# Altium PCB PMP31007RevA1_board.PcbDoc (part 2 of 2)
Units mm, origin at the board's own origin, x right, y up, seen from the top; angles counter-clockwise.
Board outline 45.72 x 49.53 mm, 2 copper layers (Top Layer, Bottom Layer), stack 1.575 mm thick; 68 components, 31 nets, 155 pads, 66 vias.
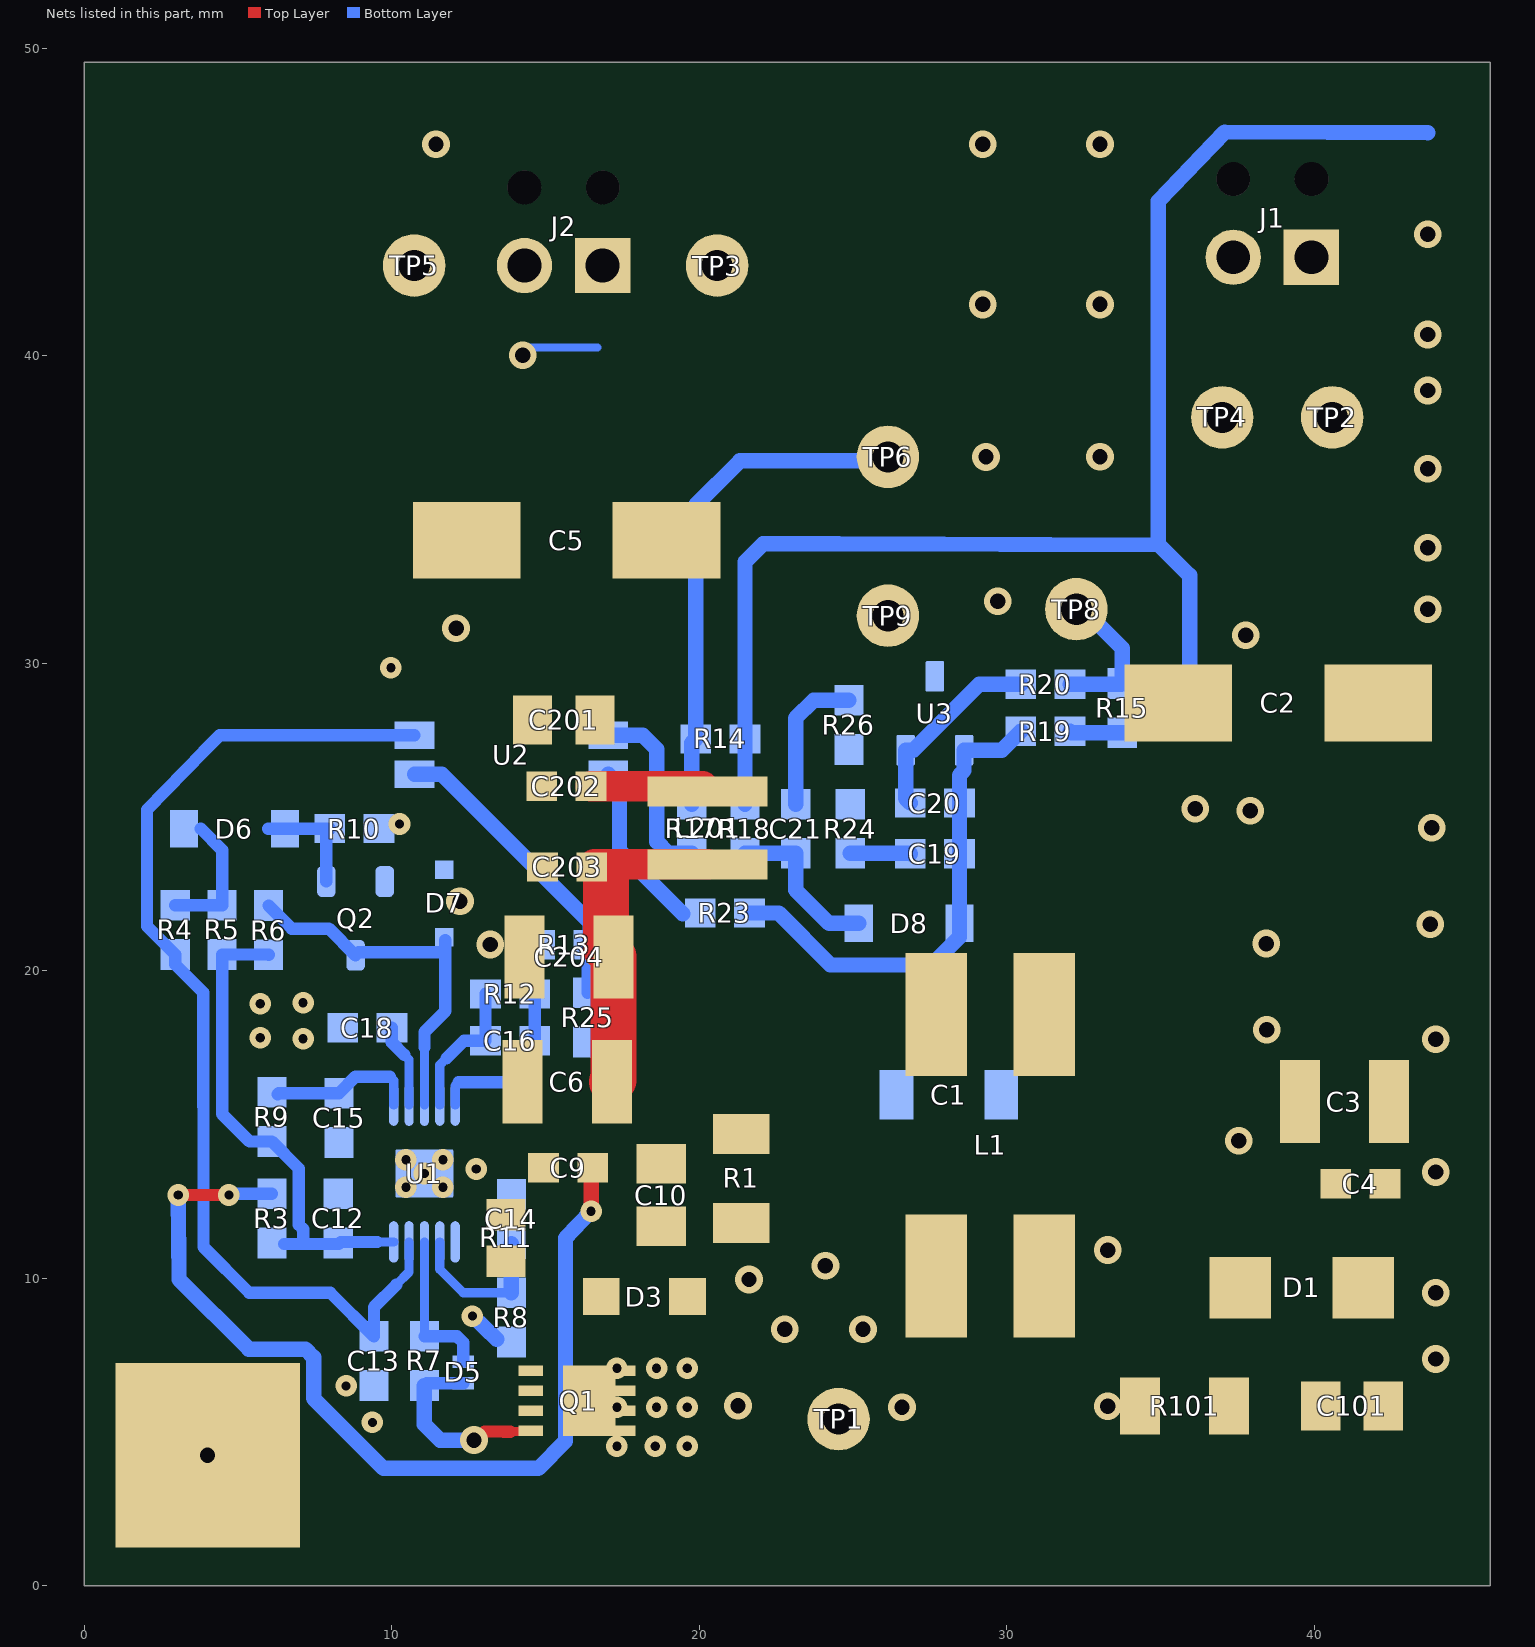
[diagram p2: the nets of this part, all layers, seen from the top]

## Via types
v1: diameter 0.9, hole 0.5, Top Layer to Bottom Layer, tented top, 21 vias
v2: diameter 0.7, hole 0.3, Top Layer to Bottom Layer, 18 vias
v3: diameter 0.9, hole 0.5, Top Layer to Bottom Layer, 17 vias
v4: diameter 0.7, hole 0.3, Top Layer to Bottom Layer, tented bottom, 9 vias
v5: diameter 0.9, hole 0.5, Top Layer to Bottom Layer, tented bottom, 1 vias

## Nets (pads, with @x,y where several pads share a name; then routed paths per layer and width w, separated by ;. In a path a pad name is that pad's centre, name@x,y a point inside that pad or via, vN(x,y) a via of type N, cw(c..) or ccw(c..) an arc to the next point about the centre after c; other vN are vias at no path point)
GND: C1.2 C5.2 C6.2 C9.2 C12.2 C13.2 C14.2 C15.2 C18.2 C201.2 C202.2 C203.2 C204.2 D7.2 J2.2 pad.1 Q2.2 R10.1 R11.1 R25.1 TP5.1 U1.6 U1.11 | length 2.5
  Bottom Layer w0.254: v3@14.137,40.259 16.681,40.259
  other v2: 9.363,5.305 10.456,12.949 11.656,12.949 11.056,13.399 10.456,13.849 11.656,13.849
  other v3: 13.193,20.846 12.084,31.126 14.251,40.005 11.43,46.869
  other v4: 8.508,6.492 12.744,13.545 7.111,17.78 5.714,17.817 5.714,18.923 7.111,18.954 10.245,24.765 9.966,29.845
  other v5: 12.213,22.252
GND2: C1.1 C2.2 C3.2 C4.2 C21.2 J1.2 L1.4 R26.1 TP4.1 TP9.1 U3.3 | length 4.8
  Bottom Layer w0.5: C21.2@23.13,25.41 23.13,28.21 23.706,28.786 R26.1@24.86,28.786
  other v1: 37.914,25.201 36.122,25.26 37.762,30.898 29.698,32.004 29.319,36.703 33.023,36.709 29.213,41.662 33.026,41.662 29.213,46.869 33.023,46.869
  other v3: 37.534,14.469 38.449,18.072 38.429,20.876
NetC6_1: C6.1 C9.1 C10.1 C203.1 C204.1 L1.3 L201.2 R1.2 R3.2 | length 41.4
  Top Layer w0.254: C9.1@16.475,13.533 C9.1@16.531,13.589 ; C203.1@16.493,23.368 C203.1@16.578,23.453
  Top Layer w0.4: v2(3.047,12.7) v4(4.698,12.7)
  Top Layer w0.5: v2(16.475,12.171) C9.1@16.475,13.533
  Top Layer w1: C203.1@16.578,23.453 L201.2@20.266,23.453
  Top Layer w1.5: C204.1@16.959,20.701 16.959,22.844 ; C6.1@17.151,16.383 17.209,16.441 C204.1@17.209,20.447
  Bottom Layer w0.4: v4(4.698,12.7) 4.736,12.738 R3.2@6.095,12.738
  Bottom Layer w0.5: v2(3.047,12.7) 3.076,9.953 5.343,7.685 7.187,7.685 7.451,7.422 7.451,6.085 9.726,3.811 14.759,3.811 15.642,4.693 15.642,11.303 v2(16.475,12.171)
NetC10_2: C10.2 D3.1 R1.1
NetC12_1: C12.1 R3.1 R5.2 R6.2 R9.2 U1.10 | length 16
  Bottom Layer w0.3: 9.526,11.174 U1.10@10.056,11.174
  Bottom Layer w0.4: R6.2@5.988,20.513 5.98,20.521 R5.2@4.476,20.521 4.476,15.334 5.371,14.44 R9.2@6.095,14.44 6.97,13.565 6.97,11.731 7.111,11.59 7.111,11.108 ; R3.1@6.492,11.108 7.111,11.108 ; 9.526,11.174 8.336,11.174 8.27,11.108 7.111,11.108
NetC14_1: C14.1 R8.1 U1.7 | length 5.1
  Bottom Layer w0.3: U1.7@11.556,11.174 11.556,10.285 12.319,9.521 R8.1@13.884,9.521
  Bottom Layer w0.5: R8.1@13.884,9.521 C14.1@13.884,11.124
NetC15_1: C15.1 R9.1 U1.1 | length 4.9
  Bottom Layer w0.3: 9.927,16.549 10.056,16.42 U1.1@10.056,15.624
  Bottom Layer w0.4: R9.1@6.284,15.972 6.322,16.01 C15.1@8.278,16.01 8.817,16.549 9.927,16.549
NetC16_1: C16.1 R12.2 U1.4 | length 4.6
  Bottom Layer w0.3: U1.4@11.556,15.624 11.556,16.93 11.77,17.145
  Bottom Layer w0.4: 11.77,17.145 12.342,17.717 C16.1@13.044,17.717 R12.2@13.044,19.241
NetC16_2: C16.2 R12.1 R13.2 U1.5 | length 7.4
  Bottom Layer w0.3: U1.5@12.056,15.624 12.056,16.256 12.163,16.364
  Bottom Layer w0.4: 12.163,16.364 13.975,16.364 14.644,17.032 C16.2@14.644,17.717 R12.1@14.644,19.241 14.644,20.685 R13.2@14.8,20.841
NetC18_1: C18.1 U1.2 | length 2.7
  Bottom Layer w0.3: 10.395,17.263 10.556,17.102 U1.2@10.556,15.624
  Bottom Layer w0.4: C18.1@9.997,18.138 9.997,17.661 10.395,17.263
NetC19_1: C19.1 R24.1 | length 2
  Bottom Layer w0.5: R24.1@24.902,23.81 26.839,23.81 C19.1@26.854,23.795
NetC19_2: C19.2 C20.1 D8.2 R19.1 R23.1 U3.1 | length 16.1
  Bottom Layer w0.5: R23.1@21.628,21.871 22.578,21.871 24.257,20.178 27.545,20.178 28.454,21.087 C19.2@28.454,23.795 C20.1@28.454,25.446 28.454,26.353 28.604,26.503 U3.1@28.604,27.167 29.833,27.167 R19.1@30.448,27.783
NetC20_2: C20.2 R20.1 R24.2 R26.2 U3.2 | length 6.4
  Bottom Layer w0.5: C20.2@26.854,25.446 26.704,25.596 U3.2@26.704,27.167 26.954,27.167 29.094,29.307 R20.1@30.448,29.307
NetC21_1: C21.1 D8.1 R18.1 | length 5.3
  Bottom Layer w0.5: R18.1@21.479,23.81 C21.1@23.13,23.81 23.13,22.62 24.216,21.533 D8.1@25.18,21.533
NetC101_2: C101.2 R101.2
NetD1_2: D1.2 L1.2 R101.1
  other v1: 33.277,5.829 33.277,10.909
NetD3_2: D3.2 L1.1 Q1.5 Q1.6 Q1.7 Q1.8 Q1.9 TP1.1
  other v1: 26.587,5.798 22.777,8.338 25.317,8.338 21.611,9.953 24.096,10.397
  other v2: 17.316,4.528 18.563,4.528 19.602,4.528 17.316,5.798 18.605,5.798 19.602,5.798 17.316,7.068 18.605,7.068 19.602,7.068
  other v3: 21.253,5.842
NetD5_1: D5.1 R7.2 U1.8 | length 5
  Bottom Layer w0.3: R7.2@11.056,8.103 U1.8@11.056,11.174
  Bottom Layer w0.4: R7.2@11.056,8.103 12.118,8.103 12.318,7.903 D5.1@12.318,7.282
NetD5_2: D5.2 Q1.4 R7.1 | length 6.6
  Top Layer w0.254: v3(12.668,4.73) 12.73,4.73 v3@13.007,5.007 ; 13.844,5.004 13.846,5.007
  Top Layer w0.3: 13.846,5.007 Q1.4@14.546,5.007
  Top Layer w0.4: v3@13.007,5.007 13.216,5.006 13.634,5.005 13.844,5.004
  Top Layer w0.5: v3(12.668,4.73) v3@12.811,4.587
  Bottom Layer w0.4: R7.1@11.056,6.503 11.135,6.582 D5.2@12.318,6.582
  Bottom Layer w0.5: R7.1@11.056,6.503 11.056,5.236 11.562,4.73 v3(12.668,4.73)
NetD6_1: D6.1 R4.1 R5.1 | length 4.3
  Bottom Layer w0.4: R4.1@2.952,22.121 R5.1@4.476,22.121 4.476,23.918 3.779,24.615
NetD6_2: D6.2 Q2.1 R10.2 | length 3.8
  Bottom Layer w0.4: 5.979,24.615 R10.2@7.978,24.615 7.866,24.503 Q2.1@7.866,22.894
NetD7_1: D7.1 Q2.3 R6.1 U1.3 | length 12
  Bottom Layer w0.3: U1.3@11.056,15.624 11.056,17.507
  Bottom Layer w0.4: R6.1@5.988,22.113 6.739,21.362 7.948,21.362 Q2.3@8.816,20.494 ; Q2.3@8.916,20.594 11.737,20.594 ; 11.056,17.507 11.056,18.003 11.737,18.684 D7.1@11.737,20.994
NetQ1_1: Q1.1 Q1.2 Q1.3 R8.2 R11.2 | length 1.1
  Bottom Layer w0.5: v2(12.617,8.763) R8.2@13.409,8.008
NetR13_1: R13.1 R25.2 U2.3 | length 10
  Bottom Layer w0.4: R25.2@16.362,19.279 16.362,20.803 R13.1@16.4,20.841 16.4,21.599
  Bottom Layer w0.5: U2.3@10.734,26.378 11.621,26.378 16.4,21.599
NetR14_1: R14.1 R17.2 TP6.1 | length 16.7
  Bottom Layer w0.5: R17.2@19.748,25.41 19.748,27.401 R14.1@19.879,27.531 19.879,35.139 21.316,36.576 26.003,36.576 TP6.1@26.13,36.703
NetR15_2: R15.2 R20.2 TP8.1 | length 4.3
  Bottom Layer w0.5: R20.2@32.048,29.307 33.721,29.307 R15.2@33.75,29.336 33.75,30.48 TP8.1@32.734,31.496
NetR17_1: R17.1 U2.1 | length 6.1
  Bottom Layer w0.5: U2.1@17.034,27.648 18.156,27.648 18.614,27.19 18.614,24.19 18.994,23.81 R17.1@19.748,23.81
NetR23_2: R23.2 U2.2 | length 5.5
  Bottom Layer w0.5: U2.2@17.034,26.378 17.399,26.013 17.399,23.904 19.455,21.848
VBP: C13.1 R4.2 U1.9 U2.4 | length 35
  Bottom Layer w0.3: 10.138,9.779 10.556,10.197 U1.9@10.556,11.174
  Bottom Layer w0.4: 10.138,9.779 9.413,9.054 C13.1@9.413,8.103 7.995,9.521 5.357,9.521 3.872,11.006 3.872,11.77 3.864,19.284 2.952,20.196 R4.2@2.952,20.521 2.031,21.442 2.031,25.229 3.883,27.134 4.396,27.648 U2.4@10.734,27.648
VIN: C5.1 C201.1 C202.1 J2.1 L201.1 TP3.1 | length 3.9
  Top Layer w0.254: L201.1@20.097,25.991 L201.1@20.266,25.823
  Top Layer w1: C202.1@16.471,25.991 L201.1@20.097,25.991
VOUT: C2.1 C3.1 C4.1 C101.1 D1.1 J1.1 R14.2 R15.1 R18.2 R19.2 TP2.1 | length 52.3
  Bottom Layer w0.5: R18.2@21.479,25.41 R14.2@21.479,27.531 21.479,33.292 22.065,33.878 24.529,33.878 34.925,33.84 ; R19.2@32.048,27.783 32.095,27.736 R15.1@33.75,27.736 34.893,27.736 35.94,28.783 35.94,32.849 34.95,33.839 34.925,33.84 ; 43.688,47.244 37.084,47.268 34.925,45.025 34.925,33.84
  other v1: 43.945,7.366 43.945,9.525 43.815,24.638 43.688,31.75
  other v3: 43.945,13.449 43.945,17.767 43.762,21.507 43.688,33.746 43.688,36.322 43.688,38.862 43.688,40.684 43.688,43.942
pads on no net: J1.MH1 J1.MH2 J2.MH1 J2.MH2

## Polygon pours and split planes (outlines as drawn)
VIN on Top Layer "TOP_LAYER_VIN_P068" (solid, remove dead copper, pour order 68): 15.96,48.006 22.164,48.006 22.164,41.74 21.421,40.998 21.421,30.844 17.221,26.644 17.221,25.266 15.993,25.266 15.96,25.299
GND on Top Layer "TOP_LAYER_GND_P062" (solid, remove dead copper, pour order 62): 8.966,48.006 15.415,48.006 15.415,19.865 8.966,19.865 8.966,42.185
GND on Top Layer "TOP_LAYER_GND_P034" (solid, remove dead copper, pour order 34): 11.669,11.59 10.032,9.953 10.032,5.992 12.214,3.81 12.182,3.842 1.682,3.81 1.65,3.842 1.65,22.252 5.939,24.638 11.656,24.638 11.656,12.949
VOUT on Top Layer "TOP_LAYER_VOUT_P028" (solid, remove dead copper, pour order 28): 38.821,41.785 38.821,36.383 38.821,28.677 41.583,25.915 41.583,3.965 44.45,3.965 44.45,48.006 38.821,48.006
NetC101_2 on Top Layer "TOP_LAYER_NETC101_2_P024" (solid, remove dead copper, pour order 24): 36.409,6.731 36.409,3.867 40.854,3.867 40.854,6.698 ccw(c40.313,6.698) 40.313,7.239 36.917,7.239 ccw(c36.917,6.731)
NetD1_2 on Top Layer "TOP_LAYER_NETD1_2_P022" (solid, remove dead copper, pour order 22): 30.098,12.065 30.098,3.937 37.232,3.937 37.232,12.182 30.225,12.182 30.204,12.171 ccw(c30.204,12.065)
GND2 on Top Layer "TOP_LAYER_GND2_P020" (solid, remove dead copper, pour order 20): 38.353,26.797 33.833,26.797 30.15,30.48 24.935,30.48 23.875,31.54 23.875,46.818 25.062,48.006 38.353,48.006
GND2 on Top Layer "TOP_LAYER_GND2_P018" (solid, remove dead copper, pour order 18): 36.068,12.7 34.827,12.7 34.183,13.344 27.873,13.344 26.415,14.802 26.415,20.65 28.749,20.65 28.749,15.24 36.068,15.24
GND2 on Top Layer "TOP_LAYER_GND2_P016" (solid, remove dead copper, pour order 16): 39.948,26.938 41.105,25.781 41.105,12.401 40.897,12.193 35.334,12.193 33.782,13.745 33.782,26.938
GND on Top Layer "TOP_LAYER_GND_P014" (solid, remove dead copper, pour order 14): 14.477,11.557 10.108,11.557 7.403,14.262 7.403,21.522 15.415,21.522 15.415,12.348
NetQ1_1 on Top Layer "TOP_LAYER_NETQ1_1_P012" (solid, remove dead copper, pour order 12): 14.985,5.588 11.683,5.588 10.667,6.604 10.667,10.104 11.612,11.049 14.35,11.049 14.985,10.414
NetD3_2 on Top Layer "TOP_LAYER_NETD3_2_P010" (solid, remove dead copper, pour order 10): 28.838,12.022 ccw(c28.733,12.022) 28.733,12.128 18.988,12.128 ccw(c18.99,11.753) 18.615,11.751 ccw(c19.297,11.684) 18.612,11.684 cw(c16.39,11.684) 17.961,10.113 17.594,9.746 cw(c16.788,10.552) 16.788,9.412 16.213,9.412 ccw(c16.213,8.75) 15.551,8.75 15.551,3.937 28.847,3.937 28.847,11.938 ccw(c28.417,11.938)
NetC10_2 on Top Layer "TOP_LAYER_NETC10_2_P008" (solid, remove dead copper, pour order 8): 15.936,12.676 15.936,8.624 ccw(c16.255,8.624) 16.255,8.305 17.06,8.305 ccw(c17.06,8.762) 17.517,8.762 17.517,9.109 cw(c18.173,9.109) 17.709,9.573 18.478,10.342 cw(c19.811,9.009) 19.811,10.894 20.085,10.894 ccw(c20.085,11.583) 20.573,11.096 ccw(c20.266,11.402) 20.7,11.402 20.7,12.676
NetC6_1 on Top Layer "TOP_LAYER_NETC6_1_P006" (solid, remove dead copper, pour order 6): 29.569,21.866 22.865,21.866 22.855,29.134 29.433,29.134 32.258,26.309 32.258,19.861 30.098,19.861 30.098,21.338
NetC6_1 on Top Layer "TOP_LAYER_NETC6_1_P004" (solid, remove dead copper, pour order 4): 22.86,20.127 21.475,17.653 16.001,17.653 16.001,13.081 23.622,13.081 24.702,14.161 24.702,24.822 22.86,24.822
GND on Bottom Layer "BOTTOM_LAYER_GND_P066" (solid, remove dead copper, pour order 66): 22.54,48.006 12.617,48.006 12.617,38.481 21.146,38.481 22.54,40.386
VOUT on Bottom Layer "BOTTOM_LAYER_VOUT_P060" (solid, remove dead copper, pour order 60): 43.264,3.871 41.613,5.522 41.613,48.006 44.45,48.006 44.45,3.86
NetD1_2 on Bottom Layer "BOTTOM_LAYER_NETD1_2_P058" (solid, remove dead copper, pour order 58): 30.098,12.065 30.098,3.973 41.655,3.973 41.655,11.293 ccw(c40.766,11.293) 40.766,12.182 30.225,12.182 30.204,12.171 ccw(c30.204,12.065)
NetD3_2 on Bottom Layer "BOTTOM_LAYER_NETD3_2_P056" (solid, remove dead copper, pour order 56): 16.837,3.81 16.837,9.04 cw(c18.836,9.04) 18.836,11.039 26.986,11.039 cw(c26.973,9.165) 28.847,9.152 28.847,3.81
NetC20_2 on Bottom Layer "BOTTOM_LAYER_NETC20_2_P046" (solid, remove dead copper, pour order 46): 27.527,24.765 27.527,27.783 24.237,27.783 24.237,24.765
GND2 on Bottom Layer "BOTTOM_LAYER_GND2_P044" (solid, remove dead copper, pour order 44): 30.095,12.545 41.092,12.545 41.092,47.879 27.478,47.879 27.478,28.963 37.445,22.63 37.445,17.054 30.582,17.054 30.095,16.567
GND2 on Bottom Layer "BOTTOM_LAYER_GND2_P042" (solid, remove dead copper, pour order 42): 22.733,28.194 27.354,28.194 28.162,29.002 28.162,32.727 27.679,33.211 23.475,33.211 22.733,32.468 22.733,29.6
GND on Bottom Layer "BOTTOM_LAYER_GND_P040" (solid, remove dead copper, pour order 40): 27.08,18.669 20.193,18.669 16.383,22.479 13.208,22.479 13.208,48.006 1.397,48.006 0.984,47.593 0.984,3.81 16.225,3.81 16.225,8.957 18.807,11.539 26.169,11.538 27.686,13.056 27.686,17.963

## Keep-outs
Keep-Out Layer:
  text ".Layer_Name" at 14.656,-21.806 h1.52

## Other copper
Top Layer:
  text ".Layer_Name" at 14.656,-21.806 h1.52
Bottom Layer:
  pour cut-out: 9.569,15.069 9.569,14.648 9.95,14.267 12.347,14.267 12.616,14.536 12.616,15.099
  pour cut-out: 9.512,11.786 9.512,12.151 9.89,12.529 11.474,12.529 11.855,12.148 11.855,11.77
  text ".Layer_Name" at 14.656,-21.806 h1.52

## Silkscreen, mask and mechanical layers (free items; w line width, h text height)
Top Overlay:
  lines w0.25: 12.809,4.064 43.149,4.064 43.149,29.179 12.809,29.179 12.809,4.064
  text "VOUT" at 39.54,47.132 h1
  text "GND2" at 34.46,47.005 h1
  text "GND" at 12.484,46.736 h1
  text "VIN" at 16.722,46.736 h1
  text "NWA" at 24.702,38.481 h1
  text "NWA" at 27.94,31.126 h1
  text "2021/02" at 45.085,30.988 h1 r90
  text "GND2" at 20.457,29.845 h1
  text "'.PRJ_Number' '.PCB_Rev'" at 3.242,29.083 h1.85 r90
  text "TPS40210 Flyback" at 45.085,5.035 h1.5 r90
  text ".Layer_Name" at 14.656,-21.806 h1.52
Bottom Overlay:
  text ".Layer_Name" at 14.656,-21.806 h1.52
Top Paste:
  text ".Layer_Name" at 14.656,-21.806 h1.52
Bottom Paste:
  text ".Layer_Name" at 14.656,-21.806 h1.52
Top Solder:
  text ".Layer_Name" at 14.656,-21.806 h1.52
  text ".Layer_Name" at 14.656,-21.806 h1.52
Bottom Solder:
  text "'.PRJ_Number' '.PCB_Rev'" at 3.302,47.498 h1.85 r90
  text ".Layer_Name" at 14.656,-21.806 h1.52
Drill Guide:
  text ".Layer_Name" at 14.656,-21.806 h1.52
M1 Board Outline:
  the board outline again, w0.254
  text ".Layer_Name" at 14.656,-21.806 h1.52
M2 Board Dimensions:
  rectangle: 3.175,-10.16 12.7,-6.985
  rectangle: 0,-6.985 3.175,-3.81
  lines w0.178: 0,-6.985 25.4,-6.985 ; 3.175,-10.16 3.175,-3.81 ; 6.35,-10.16 6.35,-3.81 ; 12.7,-10.16 12.7,-3.81 ; 19.05,-10.16 19.05,-3.81 ; 0,-10.16 0,-3.81 25.4,-3.81 25.4,-10.16 0,-10.16
  text "'.Print_Date'  '.Print_Time'" at 1.143,50.254 h1.85
  text ".Layer_Name" at 14.656,-21.806 h1.52
M3 3D STEP Top:
  text ".Layer_Name" at 14.656,-21.806 h1.52
M4 3D STEP Bottom:
  text ".Layer_Name" at 14.656,-21.806 h1.52
M5 Assembly Top:
  lines w0.254: -7.417,-23.626 160.223,-23.626 ; -7.417,-18.462 160.274,-18.462 ; -7.417,-13.297 -7.417,-28.791 94.31,-28.791 160.274,-28.791 160.274,-13.297 -7.404,-13.297 -7.404,-28.791 32.614,-28.791 ; 55.194,-28.791 55.194,-13.297 ; 87.376,-18.462 87.376,-13.297 ; 108.712,-18.462 108.712,-13.297 ; 124.511,-28.956 124.511,-23.804
  text "COMPONENTS MARKED 'DNP' SHOULD NOT BE POPULATED." at 29.299,-8.09 h1.52
  text "ASSEMBLY VARIANT:" at 29.286,-11.024 h1.52
  text ".VariantName" at 55.601,-11.024 h1.52
  text "PCB VIEWED FROM TOP SIDE" at -5.804,-16.654 h1.52
  text "BOARD #:" at 57.099,-16.654 h1.52
  text ".PRJ_Number" at 70.955,-16.654 h1.52
  text "REV:" at 92.405,-16.654 h1.52
  text ".PCB_Rev" at 99.809,-16.654 h1.52
  text "SVN REV:" at 113.69,-16.654 h1.52
  text ".VersionControl_RevNumber" at 126.543,-16.654 h1.52
  text "TID #:" at 57.099,-21.819 h1.52
  text ".TID" at 70.955,-21.819 h1.52
  text "PLOT NAME =" at -5.804,-27.034 h1.52
  text ".plot_File_Name" at 14.656,-27.034 h1.52
  text "GENERATED    :" at 57.15,-27.034 h1.52
  text ".Print_Date" at 79.235,-27.034 h1.52
  text ".Print_Time" at 97.752,-27.034 h1.52
  text "TEXAS INSTRUMENTS" at 129.87,-27.034 h1.52
M6 Assembly Bottom:
  lines w0.254: -7.429,-18.474 160.261,-18.474 ; -7.379,-23.639 160.261,-23.639 ; 28.334,-28.969 28.334,-23.817 ; 44.133,-18.474 44.133,-13.31 ; 65.468,-18.474 65.468,-13.31 ; 97.65,-28.804 97.65,-13.31 ; 120.231,-28.804 160.249,-28.804 160.249,-13.31 -7.429,-13.31 -7.429,-28.804 58.534,-28.804 160.261,-28.804 160.261,-13.31
  text "COMPONENTS MARKED 'DNP' SHOULD NOT BE POPULATED." at 154.991,-8.077 h1.52
  text ".VariantName" at 128.473,-11.024 h1.52
  text "ASSEMBLY VARIANT:" at 154.864,-11.024 h1.52
  text ".VersionControl_RevNumber" at 26.302,-16.667 h1.52
  text "SVN REV:" at 39.154,-16.667 h1.52
  text ".PCB_Rev" at 53.035,-16.667 h1.52
  text "REV:" at 60.439,-16.667 h1.52
  text ".PRJ_Number" at 81.89,-16.667 h1.52
  text "BOARD #:" at 95.745,-16.667 h1.52
  text "PCB VIEWED FROM BOTTOM SIDE" at 158.648,-16.667 h1.52
  text ".TID" at 81.89,-21.831 h1.52
  text "TID #:" at 95.745,-21.831 h1.52
  text "TEXAS INSTRUMENTS" at 22.974,-27.047 h1.52
  text ".Print_Time" at 55.093,-27.047 h1.52
  text ".Print_Date" at 73.609,-27.047 h1.52
  text "GENERATED    :" at 95.694,-27.047 h1.52
  text ".plot_File_Name" at 138.189,-27.047 h1.52
  text "PLOT NAME =" at 158.648,-27.047 h1.52
M9 Title Sheet:
  drawing of 57 lines, arcs and shapes, not listed
  text "1" at 18.792,204.127 h1.78
  text "2" at 82.182,204.127 h1.78
  text "3" at 145.411,204.127 h1.78
  text "4" at 209.08,204.127 h1.78
  text "5" at 272.555,204.127 h1.78
  text "6" at 336.182,204.127 h1.78
  text "A" at -10.579,175.095 h1.78
  text "A" at 365.341,175.095 h1.78
  text "B" at -10.579,114.643 h1.78
  text "B" at 365.341,114.643 h1.78
  text "C" at -10.579,54.318 h1.78
  text "C" at 365.341,54.318 h1.78
  text "PROJECT TITLE:" at 288.125,7.048 h1.14
  text ".PRJ_Title" at 289.395,3.662 h1.78
  text "DESIGNED FOR:" at 288.125,-0.597 h1.14
  text ".PRJ_Customer" at 289.395,-4.153 h1.78
  text "D" at -10.579,-5.88 h1.78
  text "D" at 365.341,-5.88 h1.78
  text "FILE NAME:" at 288.125,-8.217 h1.14
  text ".PCB_File_Name_No_Path" at 289.395,-11.265 h1.78
  text "Texas Instruments (TI) and/or its licensors do not warrant the accuracy or completeness of this specification" at 161.9,-15.376 h1.14
  text "ENGINEER:" at 288.125,-15.583 h1.14
  text "LAYOUT BY:" at 326.352,-15.583 h1.14
  text "or any information contained therein. TI and/or its licensors do not warrant that this design will meet" at 160.757,-18.237 h1.14
  text ".PRJ_Engineer" at 289.395,-19.52 h1.78
  text ".PCB_Layout" at 327.635,-19.52 h1.78
  text "the specifications, will be suitable for your application or fit for any particular purpose, or will operate in" at 160.757,-21.099 h1.14
  text ".Layer_Name" at 14.656,-21.806 h1.52
  text "ALTIUM DESIGNER VERSION:" at 326.352,-23.457 h1.14
  text "an implementation. TI and/or its licensors do not warrant that the design is production worthy. You should" at 160.757,-23.961 h1.14
  text "completely validate and test your design implementation to confirm the system functionality for your application." at 161.9,-26.822 h1.14
  text ".print_Scale" at 289.395,-26.843 h1.78
  text ".Application_BuildNumber" at 327.635,-26.843 h1.78
  text "1" at 18.792,-32.093 h1.78
  text "2" at 82.182,-32.093 h1.78
  text "3" at 145.411,-32.093 h1.78
  text "4" at 209.08,-32.093 h1.78
  text "5" at 272.555,-32.093 h1.78
  text "6" at 336.182,-32.093 h1.78
M10 Fab Notes:
  drawing of 189 lines, arcs and shapes, not listed
  text "DESIGN INFORMATION" at 314.503,161.447 h1.52
  text "MIN. TRACK WIDTH:" at 298.131,158.091 h1.52
  text "8" at 325.976,158.091 h1.52
  text "MIL" at 329.907,158.091 h1.52
  text "MIN. CLEARANCE:" at 298.131,154.938 h1.52
  text "0.2" at 324.452,154.938 h1.52
  text "mm" at 329.907,154.938 h1.52
  text "MIN. VIA PAD SIZE:" at 298.131,151.785 h1.52
  text "24" at 325.214,151.785 h1.52
  text "MIL" at 329.907,151.785 h1.52
  text "0.05mm (2MIL)" at 315.784,148.486 h1.52
  text "MINIMUM ANNULAR RING" at 289.769,148.277 h1.52
  text "EXTERNAL" at 333.768,148.277 h1.52
  text "PER" at 294.849,145.48 h1.52
  text "IPC-D-275 CLASS 2 LEVEL C" at 300.437,145.48 h1.52
  text "MIL, HOLES" at 338.238,142.928 h1.52
  text "+/-" at 328.27,142.709 h1.52
  text "+/-" at 349.961,142.709 h1.52
  text "REGISTRATION TOLERANCES:" at 289.769,142.682 h1.52
  text "METAL" at 320.243,142.682 h1.52
  text "5" at 334.879,142.683 h1.52
  text "3" at 356.037,142.683 h1.52
  text "MIL" at 358.99,142.682 h1.52
  text "HOLE SIZE TOLERANCE (UNLESS OTHERWISE SPECIFIED):" at 289.769,140.185 h1.52
  text "+/-" at 349.961,140.112 h1.52
  text "3" at 356.037,140.085 h1.52
  text "MIL" at 358.99,140.085 h1.52
  text "MATERIAL:" at 287.87,136.589 h1.52
  text "FR-4 High Tg" at 312.926,133.324 h1.52
  text "X" at 309.257,133.122 h1.52
  text "FR-408" at 298.563,133.007 h1.52
  text "OTHER" at 336.358,133.007 h1.52
  text "62 MIL (1.6mm) +/-10%" at 306.694,129.374 h1.52
  text "X" at 303.643,129.312 h1.52
  text "THICKNESS:" at 289.769,129.165 h1.52
  text "OTHER" at 339.33,129.165 h1.52
  text "TOLERANCE:" at 289.769,125.652 h1.52
  text "X" at 311.314,125.652 h1.52
  text "ANSI IPC-6012 TYPE 3 CLASS 2" at 315.836,125.652 h1.52
  text "OTHER +/-" at 315.835,121.989 h1.52
  text "BOW & TWIST:" at 289.769,118.302 h1.52
  text "X" at 311.314,118.302 h1.52
  text "ANSI IPC-6012 TYPE 3 CLASS 2" at 315.836,118.302 h1.52
  text "OTHER +/-" at 315.835,114.576 h1.52
  text "DRILLING:" at 287.87,111.258 h1.52
  text "NC_DRILL FILES" at 332.599,108.586 h1.52
  text "REFERENCE:" at 289.769,108.486 h1.52
  text "X" at 306.463,108.484 h1.52
  text "AS SHOWN" at 310.984,108.486 h1.52
  text "X" at 329.348,108.486 h1.52
  text "OTHER" at 340.168,104.873 h1.52
  text "PTH COPPER THICKNESS:" at 289.761,104.783 h1.52
  text "X" at 318.697,104.783 h1.52
  text "20-30 um" at 321.948,104.783 h1.52
  text "BOARD FINISH:" at 287.87,101.034 h1.52
  text "SILKSCREEN:" at 291.812,98.237 h1.52
  text "X" at 316.14,98.237 h1.52
  text "TOP" at 319.112,98.237 h1.52
  text "X" at 329.094,98.237 h1.52
  text "BOTTOM" at 332.091,98.237 h1.52
  text "SILKSCREEN COLOR:" at 291.812,94.295 h1.52
  text "X" at 316.115,94.295 h1.52
  text "WHITE" at 319.112,94.295 h1.52
  text "OTHER" at 332.091,94.295 h1.52
  text "X" at 319.442,90.652 h1.52
  text "GREEN" at 322.439,90.652 h1.52
  text "OTHER" at 338.136,90.652 h1.52
  text "SOLDER RESIST COLOR:" at 291.812,90.477 h1.52
  text "X" at 319.442,86.734 h1.52
  text "MATTE" at 322.439,86.734 h1.52
  text "SEMI-GLOSS" at 338.125,86.717 h1.52
  text "IMMERSION GOLD (ENIG)" at 314.819,82.345 h1.52
  text "ENEPIG" at 348.793,82.162 h1.52
  text "SURFACE FINISH:" at 287.87,82.136 h1.52
  text "X" at 310.298,82.136 h1.52
  text "IMM. TIN/SILVER OR EQUIV" at 296.24,78.649 h1.52
  text "OTHER" at 332.599,78.549 h1.52
  text "ARRAY/PANEL:" at 287.87,74.602 h1.52
  text "CUT AND TRIM PER M1 BOARD OUTLINE" at 314.819,74.393 h1.52
  text "N.C. ROUTE" at 314.819,70.94 h1.52
  text "X" at 332.295,70.94 h1.52
  text "V. SCORE" at 336.816,70.94 h1.52
  text "CERTIFICATION:" at 287.87,67.66 h1.52
  text "MATERIALS AND WORKMANSHIP FOR ALL PCBS" at 306.285,67.66 h1.52
  text "TO MEET OR EXCEED THE REQUIREMENTS OF:" at 306.285,65.271 h1.52
  text "X" at 297.078,62.003 h1.52
  text "ANSI IPC-A-600F CLASS ->" at 300.329,62.003 h1.52
  text "X" at 342.188,62.003 h1.52
  text "2" at 344.982,62.003 h1.52
  text "1" at 336.981,61.965 h1.52
  text "3" at 353.973,61.965 h1.52
  text "X" at 317.702,58.252 h1.52
  text "RoHS" at 320.953,58.252 h1.52
  text "OTHER" at 337.321,58.252 h1.52
  text "PER ORDER" at 347.407,58.252 h1.52
  text "ALL BOARDS MUST MEET OR EXCEED UL94-V0 REQUIREMENTS." at 288.569,54.345 h1.52
  text "PCB MUST BEAR THE UL94V-0 UL REGISTERED MATERIAL ID NUMBER" at 288.569,51.397 h1.52
  text "ADDITIONAL REQUIREMENTS:" at 287.87,47.094 h1.52
  text "MICROSECTION:" at 289.769,44.373 h1.52
  text "YES" at 312.775,44.373 h1.52
  text "REQUIRED" at 334.657,40.707 h1.52
  text "BARE BOARD ELEC. TEST:" at 289.769,40.634 h1.52
  text "NONE" at 322.935,40.634 h1.52
  text "X" at 331.66,40.634 h1.52
  text "PER ORDER" at 349.693,40.634 h1.52
  text "XX MIL VIAS REQUIRE NON-CONDUCTIVE FILL AND PLANARIZE" at 294.04,35.428 h1.5
  text "XX MIL VIAS REQUIRE CONDUCTIVE FILL AND PLANARIZE" at 294.243,32.787 h1.52
  text "OUTER XX MIL VIAS REQUIRE 50 OHM SINGLE-ENDED IMPEDANCE" at 294.218,28.637 h1.47
  text "LAYER 2 & 3 (INNER LAYERS) XX MIL WIDE, XX MIL SPACE / TRACES REQUIRE 100 OHM DIFFERENTIAL IMPEDANCE" at 294.015,22.65 h1.52
  text ".Layer_Name" at 152.927,8.535 h1.52
  text ".Layer_Name" at 14.656,-21.806 h1.52
M11 Gerber Information:
  lines w0.254: -7.417,-23.626 160.223,-23.626 ; -7.417,-18.462 160.274,-18.462 ; -7.417,-13.297 -7.417,-28.791 94.31,-28.791 160.274,-28.791 160.274,-13.297 -7.404,-13.297 -7.404,-28.791 32.614,-28.791 ; 55.194,-28.791 55.194,-13.297 ; 87.376,-18.462 87.376,-13.297 ; 108.712,-18.462 108.712,-13.297 ; 124.511,-28.956 124.511,-23.804
  text "ALL ARTWORK VIEWED FROM TOP SIDE" at -5.804,-16.654 h1.52
  text "BOARD #:" at 57.099,-16.654 h1.52
  text ".PRJ_Number" at 70.955,-16.654 h1.52
  text "REV:" at 92.405,-16.654 h1.52
  text ".PCB_Rev" at 99.809,-16.654 h1.52
  text "SVN REV:" at 113.69,-16.654 h1.52
  text ".VersionControl_RevNumber" at 126.543,-16.654 h1.52
  text "LAYER NAME =" at -5.804,-21.806 h1.52
  text "TID #:" at 57.099,-21.819 h1.52
  text ".TID" at 70.955,-21.819 h1.52
  text "PLOT NAME =" at -5.804,-27.034 h1.52
  text ".plot_File_Name" at 14.656,-27.034 h1.52
  text "GENERATED    :" at 57.15,-27.034 h1.52
  text ".Print_Date" at 79.235,-27.034 h1.52
  text ".Print_Time" at 97.752,-27.034 h1.52
  text "TEXAS INSTRUMENTS" at 129.87,-27.034 h1.52
M12 Stackup:
  drawing of 191 lines, arcs and shapes, not listed
  text "Layer" at 249.119,189.738 h1.52
  text "Name" at 259.531,189.738 h1.52
  text "Material" at 283.147,189.738 h1.52
  text "Thickness" at 304.985,189.738 h1.52
  text "Constant" at 321.49,189.738 h1.52
  text "Board Layer Stack" at 335.965,189.738 h1.52
  text "Top Overlay" at 259.531,186.69 h1.52
  text "Top Solder" at 259.531,183.642 h1.52
  text "Solder Resist" at 283.147,183.642 h1.52
  text "0.40mil" at 304.985,183.642 h1.52
  text "3.5" at 321.49,183.642 h1.52
  text "1" at 249.119,180.594 h1.52
  text "Top Layer" at 259.531,180.594 h1.52
  text "1.40mil" at 304.985,180.594 h1.52
  text "Dielectric1" at 259.531,177.546 h1.52
  text "FR-4" at 283.147,177.546 h1.52
  text "59.20mil" at 304.985,177.546 h1.52
  text "4.8" at 321.49,177.546 h1.52
  text "2" at 249.119,174.498 h1.52
  text "Bottom Layer" at 259.531,174.498 h1.52
  text "1.40mil" at 304.985,174.498 h1.52
  text "Bottom Solder" at 259.531,171.45 h1.52
  text "Solder Resist" at 283.147,171.45 h1.52
  text "0.40mil" at 304.985,171.45 h1.52
  text "3.5" at 321.49,171.45 h1.52
  text "Bottom Overlay" at 259.531,168.402 h1.52
  text ".Layer_Name" at 14.656,-21.806 h1.52
M13 Component Bodies Top:
  text ".Layer_Name" at 14.656,-21.806 h1.52
M14 Component Bodies Bottom:
  text ".Layer_Name" at 14.656,-21.806 h1.52
M15 Courtyards Top:
  text ".Layer_Name" at 14.656,-21.806 h1.52
M16 Courtyards Bottom:
  text ".Layer_Name" at 14.656,-21.806 h1.52
Drill Drawing:
  circle w0.254: c136.241,75.908 r0.703
  lines w0.254: 135.538,72.395 135.89,72.395 135.89,72.043 136.593,72.043 136.593,72.395 136.944,72.395 136.944,73.097 136.593,73.097 136.593,73.449 135.89,73.449 135.89,73.097 135.538,73.097 135.538,72.395 ; 135.538,78.368 136.241,78.719 136.944,78.368 136.593,79.071 136.944,79.773 136.241,79.422 135.538,79.773 135.89,79.071 135.538,78.368 ; 135.538,81.882 135.89,81.882 136.241,81.53 136.593,81.882 136.944,81.882 136.593,82.233 136.944,82.584 136.593,82.584 136.241,82.936 135.89,82.584 135.538,82.584 135.89,82.233 135.538,81.882 ; 135.538,86.098 136.944,86.098 136.241,84.692 135.538,86.098
  lines w0.305: 134.264,71.095 216.362,71.095 ; 134.264,86.906 216.362,86.906 ; 142.85,67.932 142.85,90.068 ; 151.287,67.932 151.287,90.068 ; 167.453,67.932 167.453,90.068 ; 174.037,67.932 174.037,90.068 ; 183.568,67.932 183.568,90.068 ; 201.972,67.932 201.972,90.068 ; 134.264,67.932 216.362,67.932 216.362,90.068 134.264,90.068 134.264,67.932
  text "Symbol" at 136.162,87.855 h1.83
  text "Quantity" at 143.799,87.855 h1.83
  text "Finished Hole Size" at 152.235,87.855 h1.83
  text "Plated" at 168.402,87.855 h1.83
  text "Hole Type" at 174.986,87.855 h1.83
  text "Drill Layer Pair" at 184.517,87.855 h1.83
  text "Hole Tolerance" at 202.92,87.855 h1.83
  text "4" at 143.799,84.692 h1.52
  text "43.31mil (1.100mm)" at 152.235,84.692 h1.52
  text "NPTH" at 168.402,84.692 h1.52
  text "Round" at 174.986,84.692 h1.52
  text "Top Layer - Bottom Layer" at 184.517,84.692 h1.52
  text "27" at 143.799,81.53 h1.52
  text "11.81mil (0.300mm)" at 152.235,81.53 h1.52
  text "PTH" at 168.402,81.53 h1.52
  text "Round" at 174.986,81.53 h1.52
  text "Top Layer - Bottom Layer" at 184.517,81.53 h1.52
  text "40" at 143.799,78.368 h1.52
  text "19.69mil (0.500mm)" at 152.235,78.368 h1.52
  text "PTH" at 168.402,78.368 h1.52
  text "Round" at 174.986,78.368 h1.52
  text "Top Layer - Bottom Layer" at 184.517,78.368 h1.52
  text "8" at 143.799,75.206 h1.52
  text "40.00mil (1.016mm)" at 152.235,75.206 h1.52
  text "PTH" at 168.402,75.206 h1.52
  text "Round" at 174.986,75.206 h1.52
  text "Top Layer - Bottom Layer" at 184.517,75.206 h1.52
  text "4" at 143.799,72.043 h1.52
  text "43.31mil (1.100mm)" at 152.235,72.043 h1.52
  text "PTH" at 168.402,72.043 h1.52
  text "Round" at 174.986,72.043 h1.52
  text "Top Layer - Bottom Layer" at 184.517,72.043 h1.52
  text "83 Total" at 143.799,68.881 h1.52
  text ".Layer_Name" at 14.656,-21.806 h1.52
M17 Embedded Cavity:
  text ".Layer_Name" at 14.656,-21.806 h1.52
M18 Embedded Assembly:
  text ".Layer_Name" at 14.656,-21.806 h1.52
M19 Embedded Keepout:
  text ".Layer_Name" at 14.656,-21.806 h1.52

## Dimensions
12.809,29.179 to 12.809,4.064 on Top Overlay
12.809,4.064 to 43.149,4.064 on Top Overlay
0,0 to 45.72,0 on M2 Board Dimensions
0,0 to 0,49.53 on M2 Board Dimensions
0,-10.16 to 25.4,-10.16 on M2 Board Dimensions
